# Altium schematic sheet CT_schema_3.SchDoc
size 299 x 185 mm
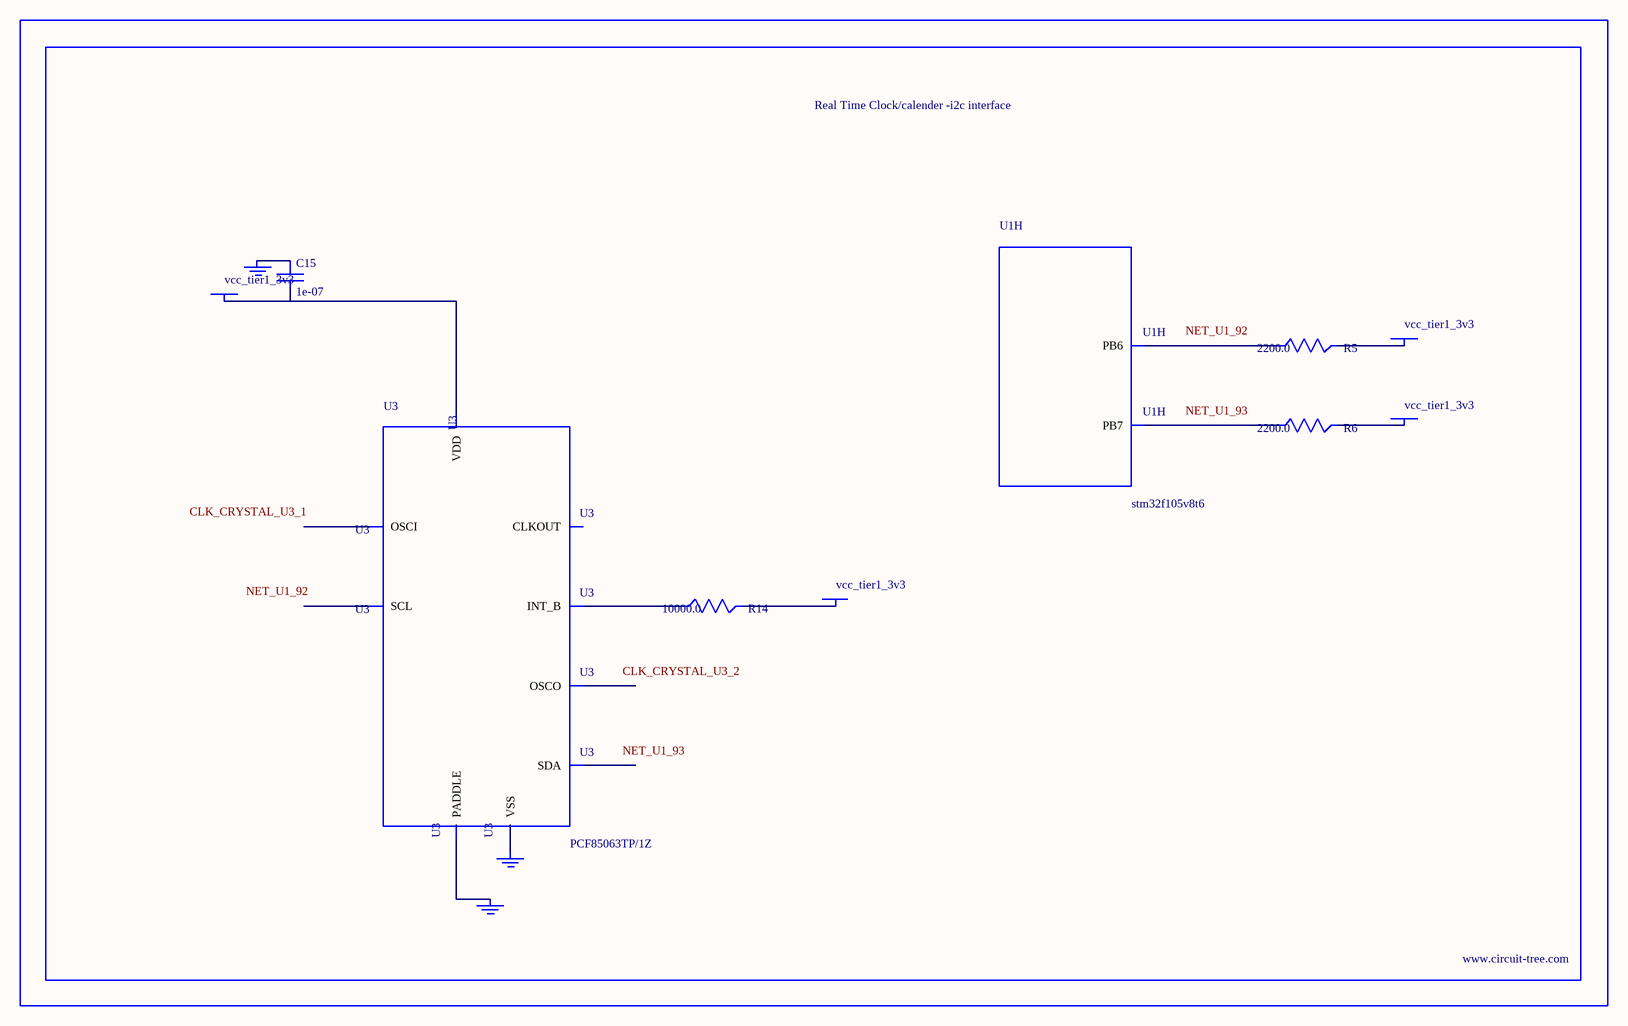
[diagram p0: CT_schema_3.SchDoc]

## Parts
BORDER2  (no value)
C15  1e-07  [C0402]
GND_INSTANCE_2_0  (no value)
GND_INSTANCE_2_1  (no value)
GND_INSTANCE_2_2  (no value)
POWER_INSTANCE_2_0  vcc_tier1_3v3
POWER_INSTANCE_2_1  vcc_tier1_3v3
POWER_INSTANCE_2_2  vcc_tier1_3v3
POWER_INSTANCE_2_3  vcc_tier1_3v3
R5  2200.0  [R0603]
R6  2200.0  [R0603]
R14  10000.0  [R0603]
U1  stm32f105v8t6  [LQFP100]  (part H of 10)
U3  PCF85063TP/1Z  [SON-8]

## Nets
NetC15_1: C15.1 GND_INSTANCE_2_0.0(GND)
NetC15_2: C15.2 POWER_INSTANCE_2_1.0(PWR) U3.8(VDD)
NetGND_INSTANCE_2_1_0: GND_INSTANCE_2_1.0(GND) U3.PAD(PADDLE)
NetGND_INSTANCE_2_2_0: GND_INSTANCE_2_2.0(GND) U3.4(VSS)
NetPOWER_INSTANCE_2_0_0: POWER_INSTANCE_2_0.0(PWR) R14.2
NetPOWER_INSTANCE_2_2_0: POWER_INSTANCE_2_2.0(PWR) R5.2
NetPOWER_INSTANCE_2_3_0: POWER_INSTANCE_2_3.0(PWR) R6.2
NetR5_1: R5.1 U1.92(PB6)
NetR6_1: R6.1 U1.93(PB7)
NetR14_1: R14.1 U3.3(INT_B)

Not connected (* = marked no-connect by the designer): U3 1(OSCI) 2(OSCO) 5(SDA) 6(SCL) 7(CLKOUT)

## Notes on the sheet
- Labels drawn without touching a wire or pin: CLK_CRYSTAL_U3_1, CLK_CRYSTAL_U3_2, NET_U1_92, NET_U1_93

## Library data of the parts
BORDER2 = BORDER_PAGE2
C15 = C0402C104K3RACTU
GND_INSTANCE_2_0-GND_INSTANCE_2_2 = GND
POWER_INSTANCE_2_0-POWER_INSTANCE_2_3 = PWR
R5 R6 = RC0603JR-072K2L
R14 = RC0603JR-0710KL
